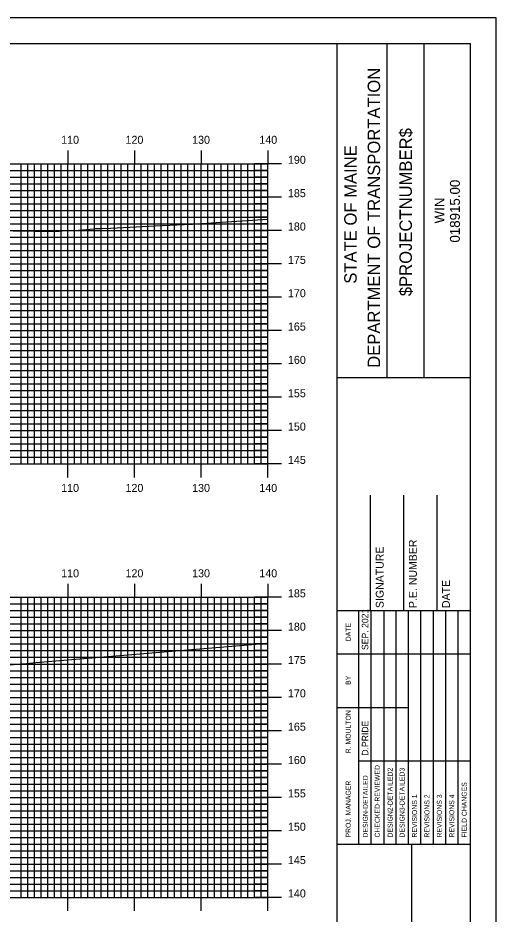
# Model space of a CAD drawing. Extents: x 1793666 to 1794009, y 442591 to 442811.
# Drawn here: x 1793933.8 to 1794005.5, y 442676.2 to 442810.5 of the extents above; entities that cross this region are included whole.
import ezdxf

# ---------------------------------------------------------------- set-up
doc = ezdxf.new("R2010")
doc.units = 0
for name, color, linetype in [('BORDER', 7, 'Continuous'), ('H_V ANNOTATION', 7, 'Continuous'), ('MAJOR', 7, 'Continuous'), ('MINOR', 7, 'Continuous'), ('PLOT BOUNDARY', 7, 'Continuous'), ('S_Roadway_Centerline', 7, 'Continuous')]:
    doc.layers.add(name, color=color, linetype=linetype)

msp = doc.modelspace()

# ---------------------------------------------------------------- linework, layer by layer
at = {"layer": 'BORDER'}
for p, q in [((1793981.71, 442596.67), (1793981.71, 442806.67)), ((1793989.17, 442756.66), (1793989.17, 442806.66)), ((1793994.76, 442756.66), (1793994.76, 442806.66)), ((1793981.72, 442756.65), (1794001.71, 442756.65)), ((1793986.71, 442721.67), (1793986.71, 442738.97)), ((1793991.71, 442721.67), (1793991.71, 442738.97)), ((1793996.71, 442721.67), (1793996.71, 442738.97)), ((1793981.71, 442721.67), (1794001.71, 442721.67)), ((1793981.71, 442686.67), (1794001.71, 442686.67)), ((1793992.9, 442616.67), (1793992.9, 442686.67))]:
    msp.add_line(p, q, dxfattribs=at)
msp.add_lwpolyline([(1793681.71, 442596.67), (1794001.71, 442596.67), (1794001.71, 442806.67), (1793681.71, 442806.67)], close=True, dxfattribs=at)
for points in [[(1793984.94, 442715.17), (1793984.94, 442721.67)], [(1793986.81, 442686.68), (1793986.81, 442721.67)], [(1793988.67, 442721.67), (1793988.67, 442686.68)], [(1793990.54, 442686.68), (1793990.54, 442721.67)], [(1793992.4, 442686.68), (1793992.4, 442721.67)], [(1793994.26, 442686.68), (1793994.26, 442721.67)], [(1793996.13, 442686.68), (1793996.13, 442721.67)], [(1793997.99, 442686.68), (1793997.99, 442721.67)], [(1793999.85, 442686.68), (1793999.85, 442721.67)], [(1793984.95, 442686.68), (1793984.95, 442720.26)], [(1793981.71, 442715.17), (1794001.71, 442715.17)], [(1793981.71, 442707.17), (1793984.95, 442707.17)], [(1793984.94, 442707.17), (1793992.4, 442707.17)], [(1793984.94, 442699.17), (1794001.71, 442699.17)]]:
    msp.add_lwpolyline(points, dxfattribs=at)
at = {"layer": 'MAJOR'}
for p, q in [((1793941.31, 442790.67), (1793941.31, 442788.67)), ((1793951.31, 442790.67), (1793951.31, 442788.67)), ((1793961.31, 442790.67), (1793961.31, 442788.67)), ((1793971.31, 442790.67), (1793971.31, 442788.67)), ((1793691.31, 442788.67), (1793971.31, 442788.67)), ((1793691.31, 442788.67), (1793971.31, 442788.67)), ((1793941.31, 442743.67), (1793941.31, 442788.67)), ((1793951.31, 442743.67), (1793951.31, 442788.67)), ((1793961.31, 442743.67), (1793961.31, 442788.67)), ((1793973.32, 442788.67), (1793969.31, 442788.67)), ((1793971.31, 442743.67), (1793971.31, 442788.67)), ((1793971.31, 442743.67), (1793971.31, 442788.67)), ((1793691.31, 442783.67), (1793971.31, 442783.67)), ((1793973.32, 442783.67), (1793969.31, 442783.67)), ((1793691.31, 442778.67), (1793971.31, 442778.67)), ((1793973.32, 442778.67), (1793969.31, 442778.67)), ((1793691.31, 442773.67), (1793971.31, 442773.67)), ((1793973.32, 442773.67), (1793969.31, 442773.67)), ((1793691.31, 442768.67), (1793971.31, 442768.67)), ((1793973.32, 442768.67), (1793969.31, 442768.67)), ((1793691.31, 442763.67), (1793971.31, 442763.67)), ((1793973.32, 442763.67), (1793969.31, 442763.67)), ((1793691.31, 442758.67), (1793971.31, 442758.67)), ((1793973.32, 442758.67), (1793969.31, 442758.67)), ((1793691.31, 442753.67), (1793971.31, 442753.67)), ((1793973.32, 442753.67), (1793969.31, 442753.67)), ((1793691.31, 442748.67), (1793971.31, 442748.67)), ((1793973.32, 442748.67), (1793969.31, 442748.67)), ((1793691.31, 442743.67), (1793971.31, 442743.67)), ((1793691.31, 442743.67), (1793971.31, 442743.67)), ((1793941.31, 442741.66), (1793941.31, 442743.67)), ((1793951.31, 442741.66), (1793951.31, 442743.67)), ((1793961.31, 442741.66), (1793961.31, 442743.67)), ((1793973.32, 442743.67), (1793969.31, 442743.67)), ((1793971.31, 442741.66), (1793971.31, 442743.67)), ((1793941.31, 442725.67), (1793941.31, 442723.67)), ((1793951.31, 442725.67), (1793951.31, 442723.67)), ((1793961.31, 442725.67), (1793961.31, 442723.67)), ((1793971.31, 442725.67), (1793971.31, 442723.67)), ((1793691.31, 442723.67), (1793971.31, 442723.67)), ((1793691.31, 442723.67), (1793971.31, 442723.67)), ((1793941.31, 442678.67), (1793941.31, 442723.67)), ((1793951.31, 442678.67), (1793951.31, 442723.67)), ((1793961.31, 442678.67), (1793961.31, 442723.67)), ((1793973.32, 442723.67), (1793969.31, 442723.67)), ((1793971.31, 442678.67), (1793971.31, 442723.67)), ((1793971.31, 442678.67), (1793971.31, 442723.67)), ((1793691.31, 442718.67), (1793971.31, 442718.67)), ((1793973.32, 442718.67), (1793969.31, 442718.67)), ((1793691.31, 442713.67), (1793971.31, 442713.67)), ((1793973.32, 442713.67), (1793969.31, 442713.67)), ((1793691.31, 442708.67), (1793971.31, 442708.67)), ((1793973.32, 442708.67), (1793969.31, 442708.67)), ((1793691.31, 442703.67), (1793971.31, 442703.67)), ((1793973.32, 442703.67), (1793969.31, 442703.67)), ((1793691.31, 442698.67), (1793971.31, 442698.67)), ((1793973.32, 442698.67), (1793969.31, 442698.67)), ((1793691.31, 442693.67), (1793971.31, 442693.67)), ((1793973.32, 442693.67), (1793969.31, 442693.67)), ((1793691.31, 442688.67), (1793971.31, 442688.67)), ((1793973.32, 442688.67), (1793969.31, 442688.67)), ((1793691.31, 442683.67), (1793971.31, 442683.67)), ((1793973.32, 442683.67), (1793969.31, 442683.67)), ((1793691.31, 442678.67), (1793971.31, 442678.67)), ((1793691.31, 442678.67), (1793971.31, 442678.67)), ((1793941.31, 442676.66), (1793941.31, 442678.67)), ((1793951.31, 442676.66), (1793951.31, 442678.67)), ((1793961.31, 442676.66), (1793961.31, 442678.67)), ((1793973.32, 442678.67), (1793969.31, 442678.67)), ((1793971.31, 442676.66), (1793971.31, 442678.67))]:
    msp.add_line(p, q, dxfattribs=at)
at = {"layer": 'MINOR'}
for p, q in [((1793934.31, 442743.67), (1793934.31, 442788.67)), ((1793935.31, 442743.67), (1793935.31, 442788.67)), ((1793936.31, 442743.67), (1793936.31, 442788.67)), ((1793937.31, 442743.67), (1793937.31, 442788.67)), ((1793938.31, 442743.67), (1793938.31, 442788.67)), ((1793939.31, 442743.67), (1793939.31, 442788.67)), ((1793940.31, 442743.67), (1793940.31, 442788.67)), ((1793942.31, 442743.67), (1793942.31, 442788.67)), ((1793943.31, 442743.67), (1793943.31, 442788.67)), ((1793944.31, 442743.67), (1793944.31, 442788.67)), ((1793945.31, 442743.67), (1793945.31, 442788.67)), ((1793946.31, 442743.67), (1793946.31, 442788.67)), ((1793947.31, 442743.67), (1793947.31, 442788.67)), ((1793948.31, 442743.67), (1793948.31, 442788.67)), ((1793949.31, 442743.67), (1793949.31, 442788.67)), ((1793950.31, 442743.67), (1793950.31, 442788.67)), ((1793952.31, 442743.67), (1793952.31, 442788.67)), ((1793953.31, 442743.67), (1793953.31, 442788.67)), ((1793954.31, 442743.67), (1793954.31, 442788.67)), ((1793955.31, 442743.67), (1793955.31, 442788.67)), ((1793956.31, 442743.67), (1793956.31, 442788.67)), ((1793957.31, 442743.67), (1793957.31, 442788.67)), ((1793958.31, 442743.67), (1793958.31, 442788.67)), ((1793959.31, 442743.67), (1793959.31, 442788.67)), ((1793960.31, 442743.67), (1793960.31, 442788.67)), ((1793962.31, 442743.67), (1793962.31, 442788.67)), ((1793963.31, 442743.67), (1793963.31, 442788.67)), ((1793964.31, 442743.67), (1793964.31, 442788.67)), ((1793965.31, 442743.67), (1793965.31, 442788.67)), ((1793966.31, 442743.67), (1793966.31, 442788.67)), ((1793967.31, 442743.67), (1793967.31, 442788.67)), ((1793968.31, 442743.67), (1793968.31, 442788.67)), ((1793969.31, 442743.67), (1793969.31, 442788.67)), ((1793970.31, 442743.67), (1793970.31, 442788.67)), ((1793691.31, 442787.67), (1793971.31, 442787.67)), ((1793691.31, 442786.67), (1793971.31, 442786.67)), ((1793971.31, 442787.67), (1793969.31, 442787.67)), ((1793971.31, 442786.67), (1793969.31, 442786.67)), ((1793691.31, 442785.67), (1793971.31, 442785.67)), ((1793971.31, 442785.67), (1793969.31, 442785.67)), ((1793691.31, 442784.67), (1793971.31, 442784.67)), ((1793971.31, 442784.67), (1793969.31, 442784.67)), ((1793691.31, 442782.67), (1793971.31, 442782.67)), ((1793971.31, 442782.67), (1793969.31, 442782.67)), ((1793691.31, 442781.67), (1793971.31, 442781.67)), ((1793971.31, 442781.67), (1793969.31, 442781.67)), ((1793691.31, 442780.67), (1793971.31, 442780.67)), ((1793691.31, 442779.67), (1793971.31, 442779.67)), ((1793971.31, 442780.67), (1793969.31, 442780.67)), ((1793971.31, 442779.67), (1793969.31, 442779.67)), ((1793691.31, 442777.67), (1793971.31, 442777.67)), ((1793971.31, 442777.67), (1793969.31, 442777.67)), ((1793691.31, 442776.67), (1793971.31, 442776.67)), ((1793691.31, 442775.67), (1793971.31, 442775.67)), ((1793971.31, 442776.67), (1793969.31, 442776.67)), ((1793971.31, 442775.67), (1793969.31, 442775.67)), ((1793691.31, 442774.67), (1793971.31, 442774.67)), ((1793971.31, 442774.67), (1793969.31, 442774.67)), ((1793691.31, 442772.67), (1793971.31, 442772.67)), ((1793691.31, 442771.67), (1793971.31, 442771.67)), ((1793971.31, 442772.67), (1793969.31, 442772.67)), ((1793971.31, 442771.67), (1793969.31, 442771.67)), ((1793691.31, 442770.67), (1793971.31, 442770.67)), ((1793971.31, 442770.67), (1793969.31, 442770.67)), ((1793691.31, 442769.67), (1793971.31, 442769.67)), ((1793971.31, 442769.67), (1793969.31, 442769.67)), ((1793691.31, 442767.67), (1793971.31, 442767.67)), ((1793971.31, 442767.67), (1793969.31, 442767.67)), ((1793691.31, 442766.67), (1793971.31, 442766.67)), ((1793971.31, 442766.67), (1793969.31, 442766.67)), ((1793691.31, 442765.67), (1793971.31, 442765.67)), ((1793971.31, 442765.67), (1793969.31, 442765.67)), ((1793691.31, 442764.67), (1793971.31, 442764.67)), ((1793971.31, 442764.67), (1793969.31, 442764.67)), ((1793691.31, 442762.67), (1793971.31, 442762.67)), ((1793971.31, 442762.67), (1793969.31, 442762.67)), ((1793691.31, 442761.67), (1793971.31, 442761.67)), ((1793971.31, 442761.67), (1793969.31, 442761.67)), ((1793691.31, 442760.67), (1793971.31, 442760.67)), ((1793691.31, 442759.67), (1793971.31, 442759.67)), ((1793971.31, 442760.67), (1793969.31, 442760.67)), ((1793971.31, 442759.67), (1793969.31, 442759.67)), ((1793691.31, 442757.67), (1793971.31, 442757.67)), ((1793971.31, 442757.67), (1793969.31, 442757.67)), ((1793691.31, 442756.67), (1793971.31, 442756.67)), ((1793691.31, 442755.67), (1793971.31, 442755.67)), ((1793971.31, 442756.67), (1793969.31, 442756.67)), ((1793971.31, 442755.67), (1793969.31, 442755.67)), ((1793691.31, 442754.67), (1793971.31, 442754.67)), ((1793971.31, 442754.67), (1793969.31, 442754.67)), ((1793691.31, 442752.67), (1793971.31, 442752.67)), ((1793691.31, 442751.67), (1793971.31, 442751.67)), ((1793971.31, 442752.67), (1793969.31, 442752.67)), ((1793971.31, 442751.67), (1793969.31, 442751.67)), ((1793691.31, 442750.67), (1793971.31, 442750.67)), ((1793971.31, 442750.67), (1793969.31, 442750.67)), ((1793691.31, 442749.67), (1793971.31, 442749.67)), ((1793971.31, 442749.67), (1793969.31, 442749.67)), ((1793691.31, 442747.67), (1793971.31, 442747.67)), ((1793971.31, 442747.67), (1793969.31, 442747.67)), ((1793691.31, 442746.67), (1793971.31, 442746.67)), ((1793971.31, 442746.67), (1793969.31, 442746.67)), ((1793691.31, 442745.67), (1793971.31, 442745.67)), ((1793971.31, 442745.67), (1793969.31, 442745.67)), ((1793691.31, 442744.67), (1793971.31, 442744.67)), ((1793971.31, 442744.67), (1793969.31, 442744.67)), ((1793934.31, 442678.67), (1793934.31, 442723.67)), ((1793935.31, 442678.67), (1793935.31, 442723.67)), ((1793936.31, 442678.67), (1793936.31, 442723.67)), ((1793937.31, 442678.67), (1793937.31, 442723.67)), ((1793938.31, 442678.67), (1793938.31, 442723.67)), ((1793939.31, 442678.67), (1793939.31, 442723.67)), ((1793940.31, 442678.67), (1793940.31, 442723.67)), ((1793942.31, 442678.67), (1793942.31, 442723.67)), ((1793943.31, 442678.67), (1793943.31, 442723.67)), ((1793944.31, 442678.67), (1793944.31, 442723.67)), ((1793945.31, 442678.67), (1793945.31, 442723.67)), ((1793946.31, 442678.67), (1793946.31, 442723.67)), ((1793947.31, 442678.67), (1793947.31, 442723.67)), ((1793948.31, 442678.67), (1793948.31, 442723.67)), ((1793949.31, 442678.67), (1793949.31, 442723.67)), ((1793950.31, 442678.67), (1793950.31, 442723.67)), ((1793952.31, 442678.67), (1793952.31, 442723.67)), ((1793953.31, 442678.67), (1793953.31, 442723.67)), ((1793954.31, 442678.67), (1793954.31, 442723.67)), ((1793955.31, 442678.67), (1793955.31, 442723.67)), ((1793956.31, 442678.67), (1793956.31, 442723.67)), ((1793957.31, 442678.67), (1793957.31, 442723.67)), ((1793958.31, 442678.67), (1793958.31, 442723.67)), ((1793959.31, 442678.67), (1793959.31, 442723.67)), ((1793960.31, 442678.67), (1793960.31, 442723.67)), ((1793962.31, 442678.67), (1793962.31, 442723.67)), ((1793963.31, 442678.67), (1793963.31, 442723.67)), ((1793964.31, 442678.67), (1793964.31, 442723.67)), ((1793965.31, 442678.67), (1793965.31, 442723.67)), ((1793966.31, 442678.67), (1793966.31, 442723.67)), ((1793967.31, 442678.67), (1793967.31, 442723.67)), ((1793968.31, 442678.67), (1793968.31, 442723.67)), ((1793969.31, 442678.67), (1793969.31, 442723.67)), ((1793970.31, 442678.67), (1793970.31, 442723.67)), ((1793691.31, 442722.67), (1793971.31, 442722.67)), ((1793971.31, 442722.67), (1793969.31, 442722.67)), ((1793691.31, 442721.67), (1793971.31, 442721.67)), ((1793691.31, 442720.67), (1793971.31, 442720.67)), ((1793971.31, 442721.67), (1793969.31, 442721.67)), ((1793971.31, 442720.67), (1793969.31, 442720.67)), ((1793691.31, 442719.67), (1793971.31, 442719.67)), ((1793971.31, 442719.67), (1793969.31, 442719.67)), ((1793691.31, 442717.67), (1793971.31, 442717.67)), ((1793691.31, 442716.67), (1793971.31, 442716.67)), ((1793971.31, 442717.67), (1793969.31, 442717.67)), ((1793971.31, 442716.67), (1793969.31, 442716.67)), ((1793691.31, 442715.67), (1793971.31, 442715.67)), ((1793971.31, 442715.67), (1793969.31, 442715.67)), ((1793691.31, 442714.67), (1793971.31, 442714.67)), ((1793971.31, 442714.67), (1793969.31, 442714.67)), ((1793691.31, 442712.67), (1793971.31, 442712.67)), ((1793971.31, 442712.67), (1793969.31, 442712.67)), ((1793691.31, 442711.67), (1793971.31, 442711.67)), ((1793971.31, 442711.67), (1793969.31, 442711.67)), ((1793691.31, 442710.67), (1793971.31, 442710.67)), ((1793971.31, 442710.67), (1793969.31, 442710.67)), ((1793691.31, 442709.67), (1793971.31, 442709.67)), ((1793971.31, 442709.67), (1793969.31, 442709.67)), ((1793691.31, 442707.67), (1793971.31, 442707.67)), ((1793971.31, 442707.67), (1793969.31, 442707.67)), ((1793691.31, 442706.67), (1793971.31, 442706.67)), ((1793971.31, 442706.67), (1793969.31, 442706.67)), ((1793691.31, 442705.67), (1793971.31, 442705.67)), ((1793691.31, 442704.67), (1793971.31, 442704.67)), ((1793971.31, 442705.67), (1793969.31, 442705.67)), ((1793971.31, 442704.67), (1793969.31, 442704.67)), ((1793691.31, 442702.67), (1793971.31, 442702.67)), ((1793971.31, 442702.67), (1793969.31, 442702.67)), ((1793691.31, 442701.67), (1793971.31, 442701.67)), ((1793691.31, 442700.67), (1793971.31, 442700.67)), ((1793971.31, 442701.67), (1793969.31, 442701.67)), ((1793971.31, 442700.67), (1793969.31, 442700.67)), ((1793691.31, 442699.67), (1793971.31, 442699.67)), ((1793971.31, 442699.67), (1793969.31, 442699.67)), ((1793691.31, 442697.67), (1793971.31, 442697.67)), ((1793691.31, 442696.67), (1793971.31, 442696.67)), ((1793971.31, 442697.67), (1793969.31, 442697.67)), ((1793971.31, 442696.67), (1793969.31, 442696.67)), ((1793691.31, 442695.67), (1793971.31, 442695.67)), ((1793971.31, 442695.67), (1793969.31, 442695.67)), ((1793691.31, 442694.67), (1793971.31, 442694.67)), ((1793971.31, 442694.67), (1793969.31, 442694.67)), ((1793691.31, 442692.67), (1793971.31, 442692.67)), ((1793971.31, 442692.67), (1793969.31, 442692.67)), ((1793691.31, 442691.67), (1793971.31, 442691.67)), ((1793971.31, 442691.67), (1793969.31, 442691.67)), ((1793691.31, 442690.67), (1793971.31, 442690.67)), ((1793691.31, 442689.67), (1793971.31, 442689.67)), ((1793971.31, 442690.67), (1793969.31, 442690.67)), ((1793971.31, 442689.67), (1793969.31, 442689.67)), ((1793691.31, 442687.67), (1793971.31, 442687.67)), ((1793971.31, 442687.67), (1793969.31, 442687.67)), ((1793691.31, 442686.67), (1793971.31, 442686.67)), ((1793691.31, 442685.67), (1793971.31, 442685.67)), ((1793971.31, 442686.67), (1793969.31, 442686.67)), ((1793971.31, 442685.67), (1793969.31, 442685.67)), ((1793691.31, 442684.67), (1793971.31, 442684.67)), ((1793971.31, 442684.67), (1793969.31, 442684.67)), ((1793691.31, 442682.67), (1793971.31, 442682.67)), ((1793691.31, 442681.67), (1793971.31, 442681.67)), ((1793971.31, 442682.67), (1793969.31, 442682.67)), ((1793971.31, 442681.67), (1793969.31, 442681.67)), ((1793691.31, 442680.67), (1793971.31, 442680.67)), ((1793971.31, 442680.67), (1793969.31, 442680.67)), ((1793691.31, 442679.67), (1793971.31, 442679.67)), ((1793971.31, 442679.67), (1793969.31, 442679.67))]:
    msp.add_line(p, q, dxfattribs=at)
at = {"layer": 'PLOT BOUNDARY'}
msp.add_lwpolyline([(1793665.53, 442590.55), (1794005.53, 442590.55), (1794005.53, 442810.55), (1793665.53, 442810.55)], close=True, dxfattribs=at)
at = {"layer": 'S_Roadway_Centerline'}
for points in [[(1793926.66, 442778.7), (1793939.51, 442778.53), (1793941.45, 442778.7), (1793942.33, 442778.67), (1793945.2, 442778.92), (1793945.46, 442778.96), (1793946.12, 442778.99), (1793947.75, 442779.02), (1793954.41, 442779.39), (1793958.76, 442779.57), (1793960, 442779.64), (1793963.55, 442779.89), (1793967.46, 442780.12), (1793971.31, 442780.35)], [(1793861.29, 442706.54), (1793862.81, 442706.91), (1793873.83, 442709.28), (1793895.29, 442710.64), (1793898.01, 442710.67), (1793898.91, 442710.78), (1793900.58, 442710.92), (1793910.57, 442711.96), (1793915.57, 442712.18), (1793922.91, 442712.77), (1793934.33, 442713.72), (1793935.11, 442713.77), (1793936.51, 442713.89), (1793953.32, 442715.27), (1793970.12, 442716.69), (1793970.84, 442716.76), (1793971.09, 442716.78), (1793971.31, 442716.81)]]:
    msp.add_lwpolyline(points, dxfattribs=at)

# ---------------------------------------------------------------- texts
at = {"layer": 'BORDER'}
for s, height, p in [('DEPARTMENT OF TRANSPORTATION', 1.8635, (1793988.13, 442758.08)), ('$PROJECTNUMBER$', 1.8635, (1793992.9, 442768.82)), ('STATE OF MAINE', 1.8635, (1793984.62, 442770.69)), ('018915.00', 1.491, (1794000.1, 442776.86)), ('WIN', 1.491, (1793997.79, 442779.73)), ('P.E. NUMBER', 1.1811, (1793993.64, 442722.06)), ('SIGNATURE', 1.181, (1793988.67, 442722.06)), ('DATE', 1.181, (1793998.6, 442722.06)), ('SEP. 2021', 0.969, (1793986.36, 442715.76)), ('DATE', 0.743, (1793983.72, 442717.08)), ('BY', 0.743, (1793983.72, 442710.54)), ('R. MOULTON', 0.745, (1793983.72, 442700.28)), ('D.PRIDE', 0.969, (1793986.36, 442699.92)), ('CHECKED-REVIEWED', 0.7455, (1793988.08, 442687.65)), ('DESIGN2-DETAILED2', 0.7455, (1793990.01, 442687.65)), ('DESIGN3-DETAILED3', 0.7455, (1793991.8, 442687.65)), ('DESIGN-DETAILED', 0.7455, (1793986.29, 442687.65)), ('PROJ. MANAGER', 0.7455, (1793983.72, 442687.65)), ('FIELD CHANGES', 0.7455, (1794001.12, 442687.65)), ('REVISIONS 1', 0.7455, (1793993.67, 442687.65)), ('REVISIONS 2', 0.7455, (1793995.53, 442687.65)), ('REVISIONS 3', 0.7455, (1793997.39, 442687.65)), ('REVISIONS 4', 0.7455, (1793999.26, 442687.65))]:
    msp.add_text(s, height=height, rotation=90, dxfattribs=at).set_placement(p)
at = {"layer": 'H_V ANNOTATION'}
for s, p in [('110', (1793940.3, 442791.67)), ('120', (1793949.95, 442791.67)), ('130', (1793959.94, 442791.67)), ('140', (1793970.02, 442791.67)), ('190', (1793974.31, 442788.67)), ('185', (1793974.31, 442783.67)), ('180', (1793974.31, 442778.67)), ('175', (1793974.31, 442773.67)), ('170', (1793974.31, 442768.67)), ('165', (1793974.31, 442763.67)), ('160', (1793974.31, 442758.67)), ('155', (1793974.31, 442753.67)), ('150', (1793974.31, 442748.67)), ('145', (1793974.31, 442743.67)), ('110', (1793940.3, 442739.47)), ('120', (1793949.95, 442739.47)), ('130', (1793959.94, 442739.47)), ('140', (1793970.02, 442739.47)), ('110', (1793940.3, 442726.67)), ('120', (1793949.95, 442726.67)), ('130', (1793959.94, 442726.67)), ('140', (1793970.02, 442726.67)), ('185', (1793974.31, 442723.67)), ('180', (1793974.31, 442718.67)), ('175', (1793974.31, 442713.67)), ('170', (1793974.31, 442708.67)), ('165', (1793974.31, 442703.67)), ('160', (1793974.31, 442698.67)), ('155', (1793974.31, 442693.67)), ('150', (1793974.31, 442688.67)), ('145', (1793974.31, 442683.67)), ('140', (1793974.31, 442678.67))]:
    msp.add_text(s, height=1.2, dxfattribs=at).set_placement(p)

doc.saveas('drawing.dxf')
